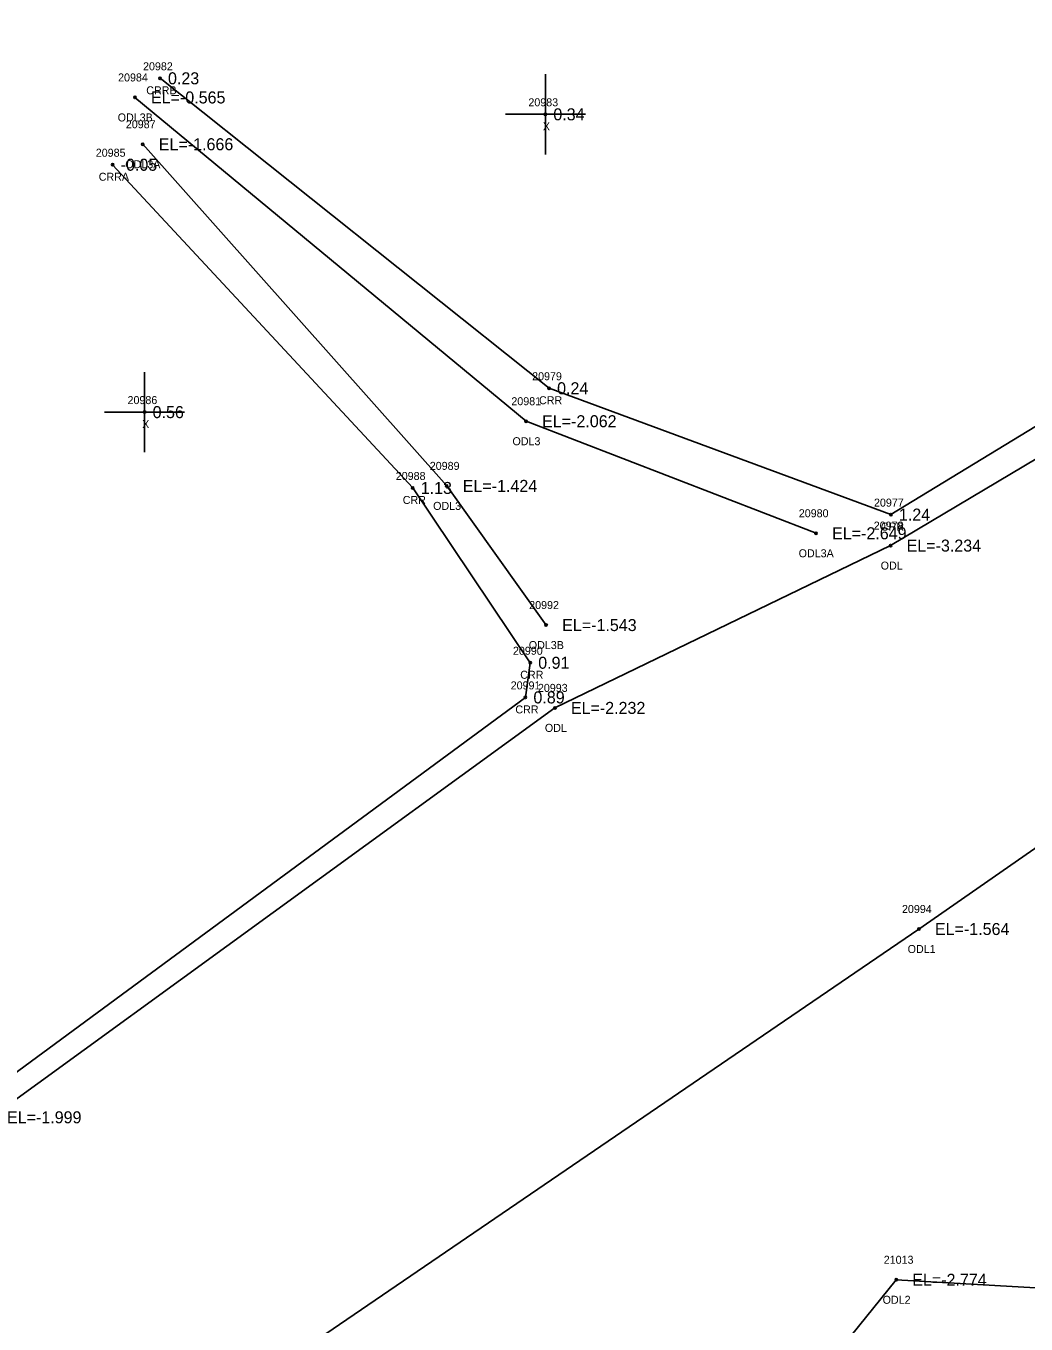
# Model space of a CAD drawing. Extents: x 2608745 to 2610333, y 641917 to 643463.
# Drawn here: x 2609261.4 to 2609386.5, y 642503 to 642665.2 of the extents above; entities that cross this region are included whole.
import ezdxf

# ---------------------------------------------------------------- set-up
doc = ezdxf.new("R2010")
doc.units = 0
for name, color, linetype in [('RD_EX_H2O', 7, 'Continuous'), ('RD_EX_H2O_txCode', 7, 'Continuous'), ('RD_EX_Misc', 7, 'Continuous'), ('RD_EX_Misc_txCode', 7, 'Continuous'), ('RD_EX_TX_H2O_ELEV', 7, 'Continuous'), ('RD_EX_TX_Misc_ELEV', 7, 'Continuous'), ('RD_SMD_Locator', 7, 'Continuous')]:
    doc.layers.add(name, color=color, linetype=linetype)

msp = doc.modelspace()

# ---------------------------------------------------------------- linework, layer by layer
at = {"layer": 'RD_EX_H2O'}
for points in [[(2609918.81, 643009.04), (2609840.99, 642946.19), (2609752.78, 642894.89), (2609679.02, 642833.68), (2609605.53, 642770.83), (2609557.42, 642733.27), (2609539.43, 642701.73), (2609511.68, 642671.53), (2609423.05, 642632.06), (2609369.55, 642600.24), (2609327.57, 642579.96), (2609257.07, 642528.8), (2609194.6, 642443.8), (2609156.56, 642341.27)], [(2609920.46, 642991.11), (2609852.12, 642929.11), (2609767.83, 642874.99), (2609693.3, 642807.6), (2609634.08, 642753.09), (2609556.79, 642686.91), (2609524.97, 642657.54), (2609444.81, 642602.16), (2609373.09, 642552.33), (2609285.68, 642492.71), (2609230.49, 642411.33), (2609205.38, 642280.88)], [(2609940.72, 642981.52), (2609865.8, 642912.86), (2609792.29, 642852.87), (2609723.77, 642786.36), (2609663.25, 642717.18), (2609610.37, 642689.46), (2609581.45, 642670.47), (2609545.26, 642637.18), (2609509.19, 642582.86), (2609482.73, 642569.2), (2609408.72, 642506.3), (2609370.25, 642508.5), (2609327.7, 642455.81), (2609283.83, 642369.21), (2609262.12, 642251.22)], [(2609477.32, 642664.29), (2609421.89, 642635.94), (2609369.59, 642604.11), (2609326.85, 642619.9), (2609278.2, 642658.63)], [(2609360.23, 642601.78), (2609323.97, 642615.78), (2609275.07, 642656.24)], [(2609276.05, 642650.39), (2609314.05, 642607.7), (2609326.48, 642590.31)], [(2609272.28, 642647.83), (2609309.8, 642607.44), (2609324.49, 642585.6), (2609323.89, 642581.27), (2609253.72, 642529.65), (2609192.07, 642445.01), (2609151.08, 642341.22)]]:
    msp.add_lwpolyline(points, dxfattribs=at)
at = {"layer": 'RD_EX_Misc'}
for p, q in [((2609326.38, 642649.13), (2609326.38, 642659.13)), ((2609321.38, 642654.13), (2609331.38, 642654.13)), ((2609276.28, 642611.92), (2609276.28, 642621.92)), ((2609271.28, 642616.92), (2609281.28, 642616.92))]:
    msp.add_line(p, q, dxfattribs=at)
at = {"layer": 'RD_SMD_Locator'}
for centre in [(2609278.2, 642658.63), (2609275.07, 642656.24), (2609326.38, 642654.13), (2609276.05, 642650.39), (2609272.28, 642647.83), (2609326.85, 642619.9), (2609276.28, 642616.92), (2609323.97, 642615.78), (2609309.8, 642607.44), (2609314.05, 642607.7), (2609369.59, 642604.11), (2609360.23, 642601.78), (2609369.55, 642600.24), (2609326.48, 642590.31), (2609324.49, 642585.6), (2609323.89, 642581.27), (2609327.57, 642579.96), (2609373.09, 642552.33), (2609370.25, 642508.5)]:
    msp.add_circle(centre, 0.15, dxfattribs=at)

# ---------------------------------------------------------------- texts
at = {"layer": 'RD_EX_H2O_txCode'}
for s, p in [('20984', (2609272.96, 642658.24)), ('20982', (2609276.08, 642659.63)), ('CRRB', (2609276.48, 642656.63)), ('ODL3B', (2609272.91, 642653.24)), ('20987', (2609273.93, 642652.39)), ('20985', (2609270.17, 642648.83)), ('ODL3A', (2609273.86, 642647.39)), ('CRRA', (2609270.54, 642645.83)), ('20979', (2609324.73, 642620.9)), ('20981', (2609322.13, 642617.78)), ('CRR', (2609325.59, 642617.9)), ('ODL3', (2609322.27, 642612.78)), ('20989', (2609311.93, 642609.7)), ('20988', (2609307.68, 642608.44)), ('CRR', (2609308.55, 642605.44)), ('ODL3', (2609312.35, 642604.7)), ('20977', (2609367.47, 642605.11)), ('20980', (2609358.07, 642603.78)), ('20978', (2609367.44, 642602.24)), ('CRR', (2609368.33, 642602.11)), ('ODL3A', (2609358.05, 642598.78)), ('ODL', (2609368.31, 642597.24)), ('20992', (2609324.36, 642592.31)), ('ODL3B', (2609324.31, 642587.31)), ('20990', (2609322.33, 642586.6)), ('CRR', (2609323.24, 642583.6)), ('20991', (2609322.05, 642582.27)), ('20993', (2609325.45, 642581.96)), ('CRR', (2609322.63, 642579.27)), ('ODL', (2609326.32, 642576.96)), ('20994', (2609370.97, 642554.33)), ('ODL1', (2609371.68, 642549.33)), ('21013', (2609368.69, 642510.5)), ('ODL2', (2609368.55, 642505.5))]:
    msp.add_text(s, height=1, dxfattribs=at).set_placement(p)
at = {"layer": 'RD_EX_Misc_txCode'}
for s, p in [('20983', (2609324.26, 642655.13)), ('X', (2609326.07, 642652.13)), ('20986', (2609274.14, 642617.92)), ('X', (2609275.97, 642614.92))]:
    msp.add_text(s, height=1, dxfattribs=at).set_placement(p)
at = {"layer": 'RD_EX_TX_H2O_ELEV'}
for s, p in [('0.23', (2609279.2, 642657.88)), ('EL=-0.565', (2609277.07, 642655.49)), ('EL=-1.666', (2609278.05, 642649.64)), ('-0.05', (2609273.28, 642647.08)), ('0.24', (2609327.85, 642619.15)), ('EL=-2.062', (2609325.97, 642615.03)), ('1.13', (2609310.8, 642606.69)), ('EL=-1.424', (2609316.05, 642606.95)), ('1.24', (2609370.59, 642603.36)), ('EL=-2.649', (2609362.23, 642601.03)), ('EL=-3.234', (2609371.55, 642599.49)), ('EL=-1.543', (2609328.48, 642589.56)), ('0.91', (2609325.49, 642584.85)), ('0.89', (2609324.89, 642580.52)), ('EL=-2.232', (2609329.57, 642579.21)), ('EL=-1.564', (2609375.09, 642551.58)), ('EL=-1.999', (2609259.07, 642528.05)), ('EL=-2.774', (2609372.25, 642507.75))]:
    msp.add_text(s, height=1.5, dxfattribs=at).set_placement(p)
at = {"layer": 'RD_EX_TX_Misc_ELEV'}
for s, p in [('0.34', (2609327.38, 642653.38)), ('0.56', (2609277.28, 642616.17))]:
    msp.add_text(s, height=1.5, dxfattribs=at).set_placement(p)

doc.saveas('drawing.dxf')
